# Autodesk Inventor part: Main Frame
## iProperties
Created: 2009-03
Part Number: Main Frame
Document SubType Name: Modeling
Designer: tangg
Density: 7.25 g/cm^3
Material: Cast Iron
Mass: 64.2851 g
Surface Area: 53.7917 cm^2
Volume: 8.86691 cm^3
Author: tangg
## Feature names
1. Extrusion1
2. Extrusion5
3. Fillet1
4. Extrusion2
